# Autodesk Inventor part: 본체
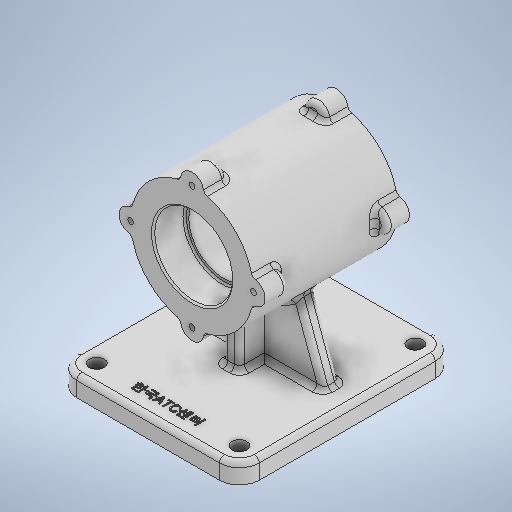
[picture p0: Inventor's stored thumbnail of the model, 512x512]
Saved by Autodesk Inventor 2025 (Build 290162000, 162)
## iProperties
Created: 2024-08
Part Number: 본체
Material: 일반
Document SubType Name: Modeling
Designer: Administrator
Density: 1 g/cm^3
Appearance: 기본값
Author: Administrator
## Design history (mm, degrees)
sketch "스케치3"
  geometry: L1 (55, 70)-(-55, 70); L2 (-55, 70)-(-55, -60); L3 (-55, -60)-(55, -60); L4 (55, -60)-(55, 70); 1 further point
  constraints: 8 end point, 2 parallel, 1 horizontal, 1 perpendicular
  dimensions: "d7" = 70 distance from line of L1 point (0, 0); "d8" = 130 distance of L3.end L1.start; "d9" = 110 distance of L2.end L3.end; "d10" = 55 distance from line of L4 point (0, 0)
extrude "돌출2" new body sketch "스케치3" distance "d11" = 12; taper "d12" = 0 deg
sketch "스케치4"
  geometry: C1 r 37 at (0, 82); 1 further point
  constraints: 1 centre point, 1 vertical alignment
  dimensions: "d13" = 82 distance of point (0, 0) C1.centre; "d15" = 37 radius of C1
extrude "돌출3" join sketch "스케치4" stored distance "d16" = 87; taper "d17" = 0 deg
fillet "모깎기1" dims "d18" = 12
sketch "스케치5"
  geometry: L1 (43, 12)-(-43, 12) reference; L2 (-55, 12)-(-43, 12) reference; L3 (43, 12)-(55, 12) reference; L4 (41, 12)-(13.165, 88.475); L5 (-41, 12)-(-13.165, 88.475); L6 (-13.165, 88.475)-(13.165, 88.475); 2 further points
  constraints: 6 end point, 2 point on line, 1 equal length
  dimensions: "d20" = 14 distance of L3.end L4.start; "d21" = 110 deg angle of L3 L4; "d22" = 14 distance of L2.start L5.start; "d23" = 110 deg angle of L2 L5
extrude "돌출4" join sketch "스케치5" stored distance "d24" = 10; taper "d25" = 0 deg
sketch "스케치6"
  geometry: L1 (-5, -20)-(5, -20); L2 (5, -20)-(5, 20); L3 (5, 20)-(-5, 20); L4 (-5, 20)-(-5, -20); L5 (-5, -20)-(5, 20); L6 (5, -20)-(-5, 20); 1 further point
  constraints: 12 end point, 2 midpoint, 2 parallel, 1 horizontal, 1 perpendicular
  dimensions: "d26" = 40 distance of L3.end L1.start; "d27" = 10 distance of L2.end L3.end
extrude "돌출5" join sketch "스케치6" distance "d28" = 70; taper "d29" = 0 deg
sketch "스케치7"
  geometry: C1 r 37 at (0, 0) reference; 2 further points
  constraints: 1 coincident
hole "구멍1" sketch "스케치7" at (0, 0) diameter "d30" = 47; stored, may be unused: countersink angle "d34" = 90 deg, drill point angle "d36" = 0 deg; dims "d31" = 6, "d32" = 4, "d33" = 2, "d35" = 19
sketch "스케치8"
  geometry: C1 r 23.5 at (0, 0) reference; 2 further points
  constraints: 1 coincident
hole "구멍2" sketch "스케치8" at (0, 0) diameter "d37" = 42; stored, may be unused: countersink angle "d41" = 90 deg, drill point angle "d43" = 0 deg; dims "d38" = 6, "d39" = 4, "d40" = 2, "d42" = 1000
sketch "스케치9"
  geometry: C1 r 37 at (0, 0) reference; 2 further points
  constraints: 1 coincident
hole "구멍3" sketch "스케치9" at (0, 0) diameter "d44" = 47; stored, may be unused: countersink angle "d48" = 90 deg, drill point angle "d50" = 0 deg; dims "d45" = 6, "d46" = 4, "d47" = 2, "d49" = 19
fillet "모깎기2" dims "d51" = 1
chamfer "모따기1" distance "d52" = 1; stored, may be unused: second distance "d53" = 2, angle "d54" = 45 deg
chamfer "모따기2" distance "d55" = 1; stored, may be unused: second distance "d56" = 2, angle "d57" = 45 deg
fillet "모깎기3" dims "d58" = 3
fillet "모깎기4" dims "d59" = 3
sketch "스케치10"
  geometry: L1 (-43, -82)-(43, -82) reference; C1 r 7 at (0, 37); 3 further points
  constraints: 2 vertical alignment, 1 centre point, 1 midpoint, 1 other
  dimensions: "d61" = 7 radius of C1
extrude "돌출6" join sketch "스케치10" distance "d62" = 14; taper "d63" = 0 deg
fillet "모깎기5" dims "d64" = 3
fillet "모깎기6" dims "d65" = 3
sketch "스케치11"
  geometry: 1 further point
sketch "스케치12"
  geometry: 1 further point
sketch "스케치13"
  geometry: A1 r 7 centre (0, 119) between (6.889, 120.239) and (-6.889, 120.239) reference; 2 further points
  constraints: 1 coincident
hole "구멍4" sketch "스케치13" at (0, 119) diameter "d66" = 3.45873; stored, may be unused: countersink angle "d70" = 90 deg, drill point angle "d72" = 120 deg; dims "d67" = 8, "d68" = 4, "d69" = 2, "d71" = 10
fillet "모깎기7" dims "d76" = 3
fillet "모깎기8" dims "d77" = 3
sketch "스케치14"
  geometry: L1 (-43, -70)-(43, -70) reference; 2 further points
  dimensions: "d82" = 12 distance from line of L1 point (43, -58); "d83" = 43 horizontal distance of point (0, 0) point (43, -58)
hole "구멍5" sketch "스케치14" at (43, -58) diameter "d84" = 9; stored, may be unused: countersink angle "d88" = 90 deg, drill point angle "d90" = 0 deg; dims "d85" = 8, "d86" = 4, "d87" = 2, "d89" = 100
sketch "스케치15"
  geometry: L1 (-43, -70)-(43, -70) reference; L2 (43, 60)-(-43, 60) reference; 4 further points
  dimensions: "d91" = 12 distance from line of L1 point (-43, -58); "d92" = 43 horizontal distance of point (0, 0) point (-43, -58); "d93" = 12 distance from line of L2 point (-43, 48); "d94" = 43 horizontal distance of point (0, 0) point (-43, 48); "d95" = 43 horizontal distance of point (0, 0) point (43, 48); "d96" = 12 distance from line of L2 point (43, 48)
hole "구멍6" sketch "스케치15" at (-43, -58), (43, 48), (-43, 48) diameter "d97" = 9; stored, may be unused: countersink angle "d101" = 90 deg, drill point angle "d103" = 0 deg; dims "d98" = 6, "d99" = 4, "d100" = 2, "d102" = 100
sketch "스케치16"
  geometry: 3 further points
  constraints: 1 coincident, 1 vertical alignment, 1 other
  dimensions: "d104" = 58 distance of point (0, -58) point (0, 0)
feature "엠보싱1" sketch "스케치16" dims "d7" = 70, "d8" = 130, "d9" = 110, "d10" = 55, "d105" = 0.5, "d106" = 0
fillet "모깎기9" dims "d107" = 3
node "솔리드2"
pattern_circular "원형 패턴1" dims angle "d74" = 360 deg
mirror "미러1"
pattern_circular "원형 패턴2" dims angle "d79" = 360 deg
mirror "미러2"
feature "A9D066F2-1C7D-4E18-AEED-F7BC21143FA4" dims "d30" = 47, "d31" = 6, "d32" = 4, "d33" = 2, "d34" = 90 deg, "d35" = 19, "d36" = 0
